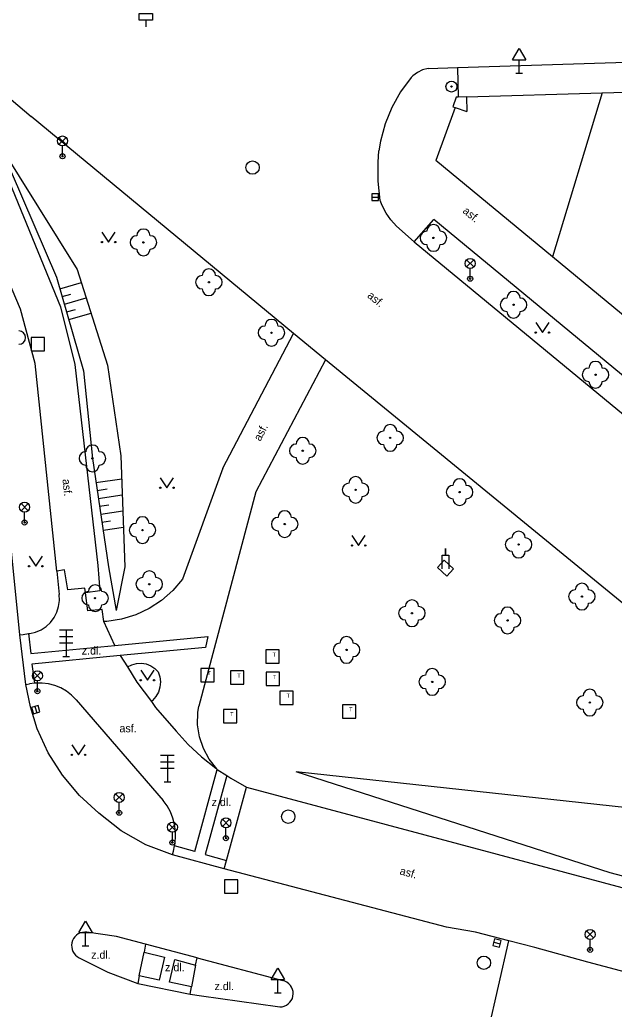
# Model space of a CAD drawing. Extents: x -642282 to -641982, y -1041678 to -1041427.
# Drawn here: x -642170.1 to -642125.6, y -1041580.5 to -1041506.3 of the extents above; entities that cross this region are included whole.
import ezdxf

# ---------------------------------------------------------------- set-up
doc = ezdxf.new("R2010")
doc.units = 0
for name, color, linetype in [('Ploty', 7, 'Continuous'), ('Pol_bod_pole', 7, 'Continuous'), ('Popis povrchů', 7, 'Continuous'), ('Rozhraní ploch 1', 7, 'Continuous'), ('Rozhraní ploch 2', 7, 'Continuous'), ('Ter_hr__hladina', 7, 'Continuous'), ('Vstup na pozemky', 7, 'Continuous'), ('Výšk_šrafy', 7, 'Continuous'), ('Zeleň - stromy', 7, 'Continuous'), ('Znaky doprava', 7, 'Continuous'), ('Znaky kanalizace', 7, 'Continuous'), ('Znaky voda', 7, 'Continuous'), ('Značky doprava', 7, 'Continuous'), ('Značky KM', 7, 'Continuous'), ('Šachta teplo', 7, 'Continuous'), ('Šachty ner_', 7, 'Continuous')]:
    doc.layers.add(name, color=color, linetype=linetype)

msp = doc.modelspace()

# ---------------------------------------------------------------- linework, layer by layer
at = {"layer": 'Ploty'}
for p, q in [((-642136.68, -1041512.12), (-642126.507, -1041511.827)), ((-642126.507, -1041511.827), (-642116.642, -1041511.542)), ((-642130.246, -1041524.117), (-642138.97, -1041516.89)), ((-642118.52, -1041533.83), (-642130.246, -1041524.117))]:
    msp.add_line(p, q, dxfattribs=at)
at = {"layer": 'Pol_bod_pole'}
for radius in [0.412, 0.05]:
    msp.add_circle((-642137.8, -1041511.35), radius, dxfattribs=at)
at = {"layer": 'Rozhraní ploch 1'}
for p, q in [((-642174.9, -1041508.88), (-642169.27, -1041513.6)), ((-642137.35, -1041509.91), (-642090.353, -1041508.419)), ((-642139.54, -1041510), (-642137.35, -1041509.91)), ((-642149.632, -1041529.862), (-642169.27, -1041513.6)), ((-642171.56, -1041516.94), (-642167.09, -1041527.87)), ((-642170.07, -1041528.03), (-642174.33, -1041518.1)), ((-642140.59, -1041523), (-642139.12, -1041521.31)), ((-642112.61, -1041543.25), (-642139.12, -1041521.31)), ((-642141.91, -1041521.82), (-642140.59, -1041523)), ((-642140.59, -1041523), (-642113.98, -1041544.965)), ((-642168.98, -1041532.12), (-642170.07, -1041528.03)), ((-642167.09, -1041527.87), (-642166.01, -1041532.18)), ((-642154.92, -1041539.96), (-642149.632, -1041529.862)), ((-642147.24, -1041531.84), (-642149.632, -1041529.862)), ((-642147.24, -1041531.84), (-642152.44, -1041541.74)), ((-642117.21, -1041556.47), (-642147.24, -1041531.84)), ((-642167.35, -1041547.67), (-642168.98, -1041532.12)), ((-642166.01, -1041532.18), (-642164.29, -1041547.24)), ((-642154.92, -1041539.96), (-642157.95, -1041548.28)), ((-642152.44, -1041541.74), (-642156.72, -1041557.79)), ((-642167.35, -1041547.67), (-642167.19, -1041549.43)), ((-642169.69, -1041556.17), (-642169.41, -1041556.13)), ((-642165.92, -1041557.31), (-642159.39, -1041564.87)), ((-642153.14, -1041563.87), (-642090.33, -1041580.69)), ((-642158.7, -1041568.93), (-642158.63, -1041568.66)), ((-642131.57, -1041575.9), (-642133.51, -1041575.39)), ((-642127.58, -1041576.99), (-642131.57, -1041575.9)), ((-642156.84, -1041576.65), (-642150.44, -1041578.37)), ((-642102.45, -1041583.73), (-642127.58, -1041576.99)), ((-642156.52, -1041579.52), (-642150.83, -1041580.32))]:
    msp.add_line(p, q, dxfattribs=at)
for points in [[(-642139.54, -1041510), (-642139.958, -1041510.106), (-642140.349, -1041510.288), (-642140.7, -1041510.538), (-642140.83, -1041510.66)], [(-642140.83, -1041510.66), (-642141.61, -1041511.746), (-642142.256, -1041512.917), (-642142.757, -1041514.156), (-642143.106, -1041515.447), (-642143.23, -1041516.16)], [(-642143.13, -1041519.89), (-642143.295, -1041518.454), (-642143.301, -1041517.009), (-642143.23, -1041516.16)], [(-642141.91, -1041521.82), (-642142.332, -1041521.349), (-642142.691, -1041520.829), (-642142.982, -1041520.268), (-642143.13, -1041519.89)], [(-642170.12, -1041552.46), (-642171.2, -1041541.67)], [(-642164.29, -1041547.24), (-642164.13, -1041549.14), (-642165.215, -1041549.289)], [(-642157.95, -1041548.28), (-642158.67, -1041549.13), (-642159.505, -1041549.868), (-642160.436, -1041550.479), (-642161.445, -1041550.95), (-642162.512, -1041551.272), (-642163.613, -1041551.438), (-642163.825, -1041551.45)], [(-642169.38, -1041552.34), (-642168.943, -1041552.239), (-642168.529, -1041552.064), (-642168.153, -1041551.819), (-642167.825, -1041551.513), (-642167.555, -1041551.154), (-642167.351, -1041550.754), (-642167.22, -1041550.324), (-642167.166, -1041549.878), (-642167.19, -1041549.43)], [(-642163.825, -1041551.45), (-642163.97, -1041550.56), (-642165.04, -1041550.64), (-642165.215, -1041549.289)], [(-642170.12, -1041552.46), (-642169.87, -1041552.42), (-642169.473, -1041552.355), (-642169.38, -1041552.34)], [(-642169.34, -1041557.852), (-642169.69, -1041556.17), (-642170.12, -1041552.46)], [(-642162.06, -1041554.86), (-642161.737, -1041554.687), (-642161.383, -1041554.589), (-642161.017, -1041554.569), (-642160.656, -1041554.629), (-642160.316, -1041554.766), (-642160.013, -1041554.973), (-642159.77, -1041555.23)], [(-642159.77, -1041555.23), (-642159.647, -1041555.596), (-642159.602, -1041555.98), (-642159.636, -1041556.365), (-642159.749, -1041556.735), (-642159.936, -1041557.073), (-642160.188, -1041557.367), (-642160.27, -1041557.44)], [(-642165.92, -1041557.31), (-642166.26, -1041556.967), (-642166.641, -1041556.672), (-642167.059, -1041556.43), (-642167.505, -1041556.246), (-642167.971, -1041556.122), (-642168.45, -1041556.061), (-642168.932, -1041556.064), (-642169.04, -1041556.08), (-642169.41, -1041556.13)], [(-642168, -1041561.292), (-642168.82, -1041559.49), (-642169.34, -1041557.852)], [(-642155.338, -1041562.535), (-642155.367, -1041562.482), (-642155.941, -1041561.766), (-642156.381, -1041560.961), (-642156.675, -1041560.092), (-642156.815, -1041559.185), (-642156.795, -1041558.267), (-642156.72, -1041557.79)], [(-642162.544, -1041567.143), (-642164.2, -1041565.81), (-642165.669, -1041564.482), (-642166.943, -1041562.967), (-642168, -1041561.292)], [(-642155.338, -1041562.535), (-642154.636, -1041563.001), (-642154.328, -1041563.206), (-642153.14, -1041563.87)], [(-642158.63, -1041568.66), (-642158.538, -1041568.269), (-642158.515, -1041568.171), (-642158.46, -1041567.671), (-642158.467, -1041567.168), (-642158.536, -1041566.67), (-642158.665, -1041566.184), (-642158.852, -1041565.717), (-642159.095, -1041565.277), (-642159.39, -1041564.87)], [(-642154.82, -1041570), (-642158.7, -1041568.93), (-642160.694, -1041568.192), (-642162.544, -1041567.143)], [(-642138.17, -1041574.37), (-642154.82, -1041570)], [(-642156.84, -1041576.65), (-642160.71, -1041575.63), (-642162.882, -1041575.073), (-642165.1, -1041574.74), (-642165.268, -1041574.732), (-642165.435, -1041574.751), (-642165.597, -1041574.798), (-642165.748, -1041574.871), (-642165.886, -1041574.968), (-642166.005, -1041575.087), (-642166.104, -1041575.223), (-642166.178, -1041575.374)], [(-642133.51, -1041575.39), (-642135.99, -1041574.73), (-642138.17, -1041574.37)], [(-642166.178, -1041575.374), (-642166.23, -1041575.55), (-642166.248, -1041575.702), (-642166.242, -1041575.87), (-642166.208, -1041576.035), (-642166.147, -1041576.192), (-642166.061, -1041576.336), (-642165.953, -1041576.465), (-642165.824, -1041576.574), (-642165.68, -1041576.66), (-642163.54, -1041577.74), (-642161.3, -1041578.58)], [(-642161.3, -1041578.58), (-642157.37, -1041579.38), (-642156.52, -1041579.52)], [(-642150.83, -1041580.32), (-642150.659, -1041580.337), (-642150.487, -1041580.325), (-642150.32, -1041580.283), (-642150.163, -1041580.213), (-642150.02, -1041580.116), (-642149.896, -1041579.997), (-642149.794, -1041579.858), (-642149.718, -1041579.703), (-642149.67, -1041579.538), (-642149.651, -1041579.367), (-642149.662, -1041579.195), (-642149.702, -1041579.028), (-642149.771, -1041578.87), (-642149.865, -1041578.726), (-642149.983, -1041578.601), (-642150.122, -1041578.498), (-642150.275, -1041578.42), (-642150.44, -1041578.37)]]:
    msp.add_lwpolyline(points, dxfattribs=at)
at = {"layer": 'Rozhraní ploch 2'}
for p, q in [((-642137.35, -1041509.91), (-642137.287, -1041512.136)), ((-642126.507, -1041511.827), (-642130.246, -1041524.117)), ((-642137.44, -1041512.14), (-642137.69, -1041512.86)), ((-642136.68, -1041512.12), (-642136.651, -1041513.221)), ((-642138.84, -1041547.39), (-642138.36, -1041546.85)), ((-642138.14, -1041548.05), (-642138.84, -1041547.39)), ((-642137.66, -1041547.51), (-642138.36, -1041546.85)), ((-642137.66, -1041547.51), (-642138.14, -1041548.05)), ((-642163.014, -1041553.237), (-642163.825, -1041551.45)), ((-642169.473, -1041552.355), (-642169.31, -1041553.84)), ((-642163.014, -1041553.237), (-642156.04, -1041552.57)), ((-642156.04, -1041552.57), (-642156.23, -1041553.39)), ((-642169.31, -1041553.84), (-642163.014, -1041553.237)), ((-642156.23, -1041553.39), (-642162.602, -1041554.003)), ((-642162.602, -1041554.003), (-642169.23, -1041554.64)), ((-642169.23, -1041554.64), (-642169.04, -1041556.08)), ((-642157.01, -1041568.69), (-642155.338, -1041562.535)), ((-642154.636, -1041563.001), (-642156.24, -1041568.92)), ((-642154.645, -1041569.36), (-642153.14, -1041563.87)), ((-642157.01, -1041568.69), (-642158.538, -1041568.269)), ((-642156.24, -1041568.92), (-642154.645, -1041569.36)), ((-642154.82, -1041570), (-642154.645, -1041569.36)), ((-642160.71, -1041575.63), (-642160.82, -1041576.23)), ((-642161.18, -1041578.02), (-642160.82, -1041576.23)), ((-642156.96, -1041577.2), (-642156.84, -1041576.65)), ((-642156.96, -1041577.2), (-642157.28, -1041578.83)), ((-642161.18, -1041578.02), (-642161.3, -1041578.58)), ((-642157.37, -1041579.38), (-642157.28, -1041578.83))]:
    msp.add_line(p, q, dxfattribs=at)
for points in [[(-642136.68, -1041512.12), (-642137.287, -1041512.136), (-642137.44, -1041512.14)], [(-642137.69, -1041512.86), (-642137.518, -1041512.92), (-642136.651, -1041513.221)], [(-642165.215, -1041549.289), (-642165.26, -1041548.94), (-642166.53, -1041549.08), (-642166.78, -1041547.58), (-642167.35, -1041547.67)], [(-642162.602, -1041554.003), (-642162.06, -1041554.86), (-642161.373, -1041556.004), (-642160.27, -1041557.44), (-642159.979, -1041557.894), (-642158.43, -1041559.66)], [(-642158.43, -1041559.66), (-642157.516, -1041560.669), (-642156.523, -1041561.6), (-642155.458, -1041562.448), (-642155.338, -1041562.535)], [(-642135.06, -1041582.18), (-642133.51, -1041575.39)], [(-642160.82, -1041576.23), (-642159.29, -1041576.6), (-642159.69, -1041578.33), (-642161.18, -1041578.02)], [(-642157.28, -1041578.83), (-642158.91, -1041578.49), (-642158.52, -1041576.79), (-642156.96, -1041577.2)]]:
    msp.add_lwpolyline(points, dxfattribs=at)
at = {"layer": 'Ter_hr__hladina'}
for p, q in [((-642171.64, -1041515.78), (-642167.38, -1041525.63)), ((-642171.64, -1041515.78), (-642165.83, -1041525.06)), ((-642165.83, -1041525.06), (-642163.55, -1041532.24)), ((-642167.38, -1041525.63), (-642165.36, -1041532.65)), ((-642165.36, -1041532.65), (-642164.69, -1041539.22)), ((-642163.55, -1041532.24), (-642162.56, -1041539.03)), ((-642164.69, -1041539.22), (-642163.49, -1041547.36)), ((-642162.56, -1041539.03), (-642162.27, -1041547.34)), ((-642163.49, -1041547.36), (-642162.91, -1041550.62)), ((-642162.27, -1041547.34), (-642162.91, -1041550.62)), ((-642125.91, -1041570.28), (-642149.42, -1041562.73)), ((-642124.62, -1041565.42), (-642149.42, -1041562.73)), ((-642100.72, -1041577.07), (-642125.91, -1041570.28))]:
    msp.add_line(p, q, dxfattribs=at)
at = {"layer": 'Vstup na pozemky'}
msp.add_line((-642137.518, -1041512.92), (-642138.97, -1041516.89), dxfattribs=at)
at = {"layer": 'Výšk_šrafy'}
for p, q in [((-642167.126, -1041526.512), (-642165.516, -1041526.049)), ((-642166.96, -1041527.088), (-642166.31, -1041526.901)), ((-642166.794, -1041527.665), (-642165.153, -1041527.193)), ((-642166.628, -1041528.242), (-642165.965, -1041528.051)), ((-642166.463, -1041528.818), (-642164.79, -1041528.336)), ((-642164.423, -1041541.033), (-642162.5, -1041540.749)), ((-642164.335, -1041541.626), (-642163.593, -1041541.517)), ((-642164.248, -1041542.22), (-642162.458, -1041541.956)), ((-642164.16, -1041542.814), (-642163.471, -1041542.712)), ((-642164.073, -1041543.407), (-642162.416, -1041543.163)), ((-642163.985, -1041544.001), (-642163.349, -1041543.907)), ((-642163.898, -1041544.594), (-642162.374, -1041544.369))]:
    msp.add_line(p, q, dxfattribs=at)
at = {"layer": 'Zeleň - stromy'}
for centre in [(-642160.87, -1041523.03), (-642139.15, -1041522.7), (-642155.97, -1041526.02), (-642133.15, -1041527.71), (-642151.28, -1041529.8), (-642127.01, -1041532.95), (-642142.39, -1041537.69), (-642148.94, -1041538.65), (-642164.69, -1041539.22), (-642144.98, -1041541.58), (-642137.19, -1041541.75), (-642150.29, -1041544.15), (-642160.94, -1041544.6), (-642132.77, -1041545.68), (-642160.43, -1041548.66), (-642164.49, -1041549.7), (-642128.03, -1041549.58), (-642140.76, -1041550.83), (-642133.6, -1041551.37), (-642145.66, -1041553.58), (-642139.24, -1041555.98), (-642127.44, -1041557.53)]:
    msp.add_circle(centre, 0.05, dxfattribs=at)
for centre, start, end in [((-642160.87, -1041522.53), 0, 180), ((-642139.65, -1041522.7), 90, 270), ((-642139.15, -1041522.2), 0, 180), ((-642138.65, -1041522.7), 270, 90), ((-642161.37, -1041523.03), 90, 270), ((-642160.37, -1041523.03), 270, 90), ((-642160.87, -1041523.53), 180, 0), ((-642139.15, -1041523.2), 180, 0), ((-642155.97, -1041525.52), 0, 180), ((-642156.47, -1041526.02), 90, 270), ((-642155.47, -1041526.02), 270, 90), ((-642155.97, -1041526.52), 180, 0), ((-642133.15, -1041527.21), 0, 180), ((-642133.65, -1041527.71), 90, 270), ((-642132.65, -1041527.71), 270, 90), ((-642133.15, -1041528.21), 180, 0), ((-642151.28, -1041529.3), 0, 180), ((-642170.2, -1041530.17), 270, 90), ((-642151.78, -1041529.8), 90, 270), ((-642150.78, -1041529.8), 270, 90), ((-642151.28, -1041530.3), 180, 0), ((-642127.51, -1041532.95), 90, 270), ((-642127.01, -1041532.45), 0, 180), ((-642126.51, -1041532.95), 270, 90), ((-642127.01, -1041533.45), 180, 0), ((-642142.39, -1041537.19), 0, 180), ((-642148.94, -1041538.15), 0, 180), ((-642142.89, -1041537.69), 90, 270), ((-642141.89, -1041537.69), 270, 90), ((-642164.69, -1041538.72), 0, 180), ((-642149.44, -1041538.65), 90, 270), ((-642148.44, -1041538.65), 270, 90), ((-642142.39, -1041538.19), 180, 0), ((-642165.19, -1041539.22), 90, 270), ((-642164.19, -1041539.22), 270, 90), ((-642148.94, -1041539.15), 180, 0), ((-642164.69, -1041539.72), 180, 0), ((-642144.98, -1041541.08), 0, 180), ((-642137.19, -1041541.25), 0, 180), ((-642145.48, -1041541.58), 90, 270), ((-642144.48, -1041541.58), 270, 90), ((-642137.69, -1041541.75), 90, 270), ((-642136.69, -1041541.75), 270, 90), ((-642144.98, -1041542.08), 180, 0), ((-642137.19, -1041542.25), 180, 0), ((-642160.94, -1041544.1), 0, 180), ((-642150.79, -1041544.15), 90, 270), ((-642150.29, -1041543.65), 0, 180), ((-642149.79, -1041544.15), 270, 90), ((-642161.44, -1041544.6), 90, 270), ((-642160.44, -1041544.6), 270, 90), ((-642160.94, -1041545.1), 180, 0), ((-642150.29, -1041544.65), 180, 0), ((-642133.27, -1041545.68), 90, 270), ((-642132.77, -1041545.18), 0, 180), ((-642132.27, -1041545.68), 270, 90), ((-642132.77, -1041546.18), 180, 0), ((-642160.93, -1041548.66), 90, 270), ((-642160.43, -1041548.16), 0, 180), ((-642159.93, -1041548.66), 270, 90), ((-642164.49, -1041549.2), 0, 180), ((-642128.03, -1041549.08), 0, 180), ((-642164.99, -1041549.7), 90, 270), ((-642163.99, -1041549.7), 270, 90), ((-642160.43, -1041549.16), 180, 0), ((-642128.53, -1041549.58), 90, 270), ((-642127.53, -1041549.58), 270, 90), ((-642164.49, -1041550.2), 180, 0), ((-642141.26, -1041550.83), 90, 270), ((-642140.76, -1041550.33), 0, 180), ((-642140.26, -1041550.83), 270, 90), ((-642133.6, -1041550.87), 0, 180), ((-642128.03, -1041550.08), 180, 0), ((-642134.1, -1041551.37), 90, 270), ((-642133.1, -1041551.37), 270, 90), ((-642140.76, -1041551.33), 180, 0), ((-642133.6, -1041551.87), 180, 0), ((-642145.66, -1041553.08), 0, 180), ((-642146.16, -1041553.58), 90, 270), ((-642145.16, -1041553.58), 270, 90), ((-642145.66, -1041554.08), 180, 0), ((-642139.74, -1041555.98), 90, 270), ((-642139.24, -1041555.48), 0, 180), ((-642138.74, -1041555.98), 270, 90), ((-642139.24, -1041556.48), 180, 0), ((-642127.94, -1041557.53), 90, 270), ((-642127.44, -1041557.03), 0, 180), ((-642126.94, -1041557.53), 270, 90), ((-642127.44, -1041558.03), 180, 0)]:
    msp.add_arc(centre, 0.5, start, end, dxfattribs=at)
at = {"layer": 'Znaky doprava'}
for p, q in [((-642167.195, -1041515.165), (-642166.665, -1041515.695)), ((-642167.195, -1041515.695), (-642166.665, -1041515.165)), ((-642166.93, -1041516.58), (-642166.93, -1041515.805)), ((-642136.665, -1041524.345), (-642136.135, -1041524.875)), ((-642136.665, -1041524.875), (-642136.135, -1041524.345)), ((-642136.4, -1041525.76), (-642136.4, -1041524.985)), ((-642170.035, -1041542.615), (-642169.505, -1041543.145)), ((-642170.035, -1041543.145), (-642169.505, -1041542.615)), ((-642169.77, -1041544.03), (-642169.77, -1041543.255)), ((-642167.15, -1041552.08), (-642166.15, -1041552.08)), ((-642167.15, -1041552.58), (-642166.15, -1041552.58)), ((-642166.65, -1041552.08), (-642166.65, -1041554.08)), ((-642166.15, -1041553.08), (-642167.15, -1041553.08)), ((-642166.9, -1041554.08), (-642166.4, -1041554.08)), ((-642169.075, -1041555.255), (-642168.545, -1041555.785)), ((-642169.075, -1041555.785), (-642168.545, -1041555.255)), ((-642168.81, -1041556.67), (-642168.81, -1041555.895)), ((-642159.58, -1041561.47), (-642158.58, -1041561.47)), ((-642159.08, -1041561.47), (-642159.08, -1041563.47)), ((-642159.58, -1041561.97), (-642158.58, -1041561.97)), ((-642158.58, -1041562.47), (-642159.58, -1041562.47)), ((-642159.33, -1041563.47), (-642158.83, -1041563.47)), ((-642162.955, -1041564.375), (-642162.425, -1041564.905)), ((-642162.955, -1041564.905), (-642162.425, -1041564.375)), ((-642162.69, -1041565.79), (-642162.69, -1041565.015)), ((-642158.965, -1041566.605), (-642158.435, -1041567.135)), ((-642158.965, -1041567.135), (-642158.435, -1041566.605)), ((-642154.955, -1041566.275), (-642154.425, -1041566.805)), ((-642154.955, -1041566.805), (-642154.425, -1041566.275)), ((-642158.7, -1041568.02), (-642158.7, -1041567.245)), ((-642154.69, -1041567.69), (-642154.69, -1041566.915)), ((-642127.685, -1041574.645), (-642127.155, -1041575.175)), ((-642127.685, -1041575.175), (-642127.155, -1041574.645)), ((-642127.42, -1041576.06), (-642127.42, -1041575.285))]:
    msp.add_line(p, q, dxfattribs=at)
for centre, radius in [((-642166.93, -1041515.43), 0.375), ((-642166.93, -1041516.58), 0.19), ((-642166.93, -1041516.58), 0.05), ((-642136.4, -1041524.61), 0.375), ((-642136.4, -1041525.76), 0.19), ((-642136.4, -1041525.76), 0.05), ((-642169.77, -1041542.88), 0.375), ((-642169.77, -1041544.03), 0.19), ((-642169.77, -1041544.03), 0.05), ((-642168.81, -1041555.52), 0.375), ((-642168.81, -1041556.67), 0.19), ((-642168.81, -1041556.67), 0.05), ((-642162.69, -1041564.64), 0.375), ((-642162.69, -1041565.79), 0.19), ((-642162.69, -1041565.79), 0.05), ((-642158.7, -1041566.87), 0.375), ((-642154.69, -1041566.54), 0.375), ((-642154.69, -1041567.69), 0.19), ((-642158.7, -1041568.02), 0.19), ((-642158.7, -1041568.02), 0.05), ((-642154.69, -1041567.69), 0.05), ((-642127.42, -1041574.91), 0.375), ((-642127.42, -1041576.06), 0.19), ((-642127.42, -1041576.06), 0.05)]:
    msp.add_circle(centre, radius, dxfattribs=at)
at = {"layer": 'Znaky kanalizace'}
for p, q in [((-642143.76, -1041519.63), (-642143.26, -1041519.63)), ((-642169.002, -1041557.821), (-642168.858, -1041558.299)), ((-642134.632, -1041575.486), (-642134.148, -1041575.614))]:
    msp.add_line(p, q, dxfattribs=at)
for points in [[(-642143.76, -1041519.88), (-642143.26, -1041519.88), (-642143.26, -1041519.38), (-642143.76, -1041519.38)], [(-642169.241, -1041557.892), (-642169.098, -1041558.371), (-642168.619, -1041558.228), (-642168.762, -1041557.749)], [(-642134.696, -1041575.727), (-642134.213, -1041575.856), (-642134.084, -1041575.373), (-642134.567, -1041575.244)]]:
    msp.add_lwpolyline(points, close=True, dxfattribs=at)
for centre in [(-642152.7, -1041517.42), (-642150.02, -1041566.08), (-642135.37, -1041577.03)]:
    msp.add_circle(centre, 0.5, dxfattribs=at)
at = {"layer": 'Znaky voda'}
msp.add_line((-642160.69, -1041506.37), (-642160.69, -1041506.87), dxfattribs=at)
msp.add_lwpolyline([(-642160.19, -1041505.87), (-642160.19, -1041506.37), (-642161.19, -1041506.37), (-642161.19, -1041505.87), (-642160.19, -1041505.87)], dxfattribs=at)
at = {"layer": 'Značky doprava'}
for p, q in [((-642133.22, -1041509.34), (-642132.72, -1041508.49)), ((-642132.72, -1041508.49), (-642132.22, -1041509.34)), ((-642133.22, -1041509.34), (-642132.22, -1041509.34)), ((-642132.72, -1041510.34), (-642132.72, -1041509.34)), ((-642132.97, -1041510.34), (-642132.47, -1041510.34)), ((-642165.71, -1041574.76), (-642165.21, -1041573.91)), ((-642165.21, -1041573.91), (-642164.71, -1041574.76)), ((-642165.71, -1041574.76), (-642164.71, -1041574.76)), ((-642165.21, -1041575.76), (-642165.21, -1041574.76)), ((-642165.459, -1041575.76), (-642164.961, -1041575.76)), ((-642151.3, -1041578.28), (-642150.8, -1041577.43)), ((-642150.8, -1041577.43), (-642150.3, -1041578.28)), ((-642151.3, -1041578.28), (-642150.3, -1041578.28)), ((-642150.8, -1041579.28), (-642150.8, -1041578.28)), ((-642151.049, -1041579.28), (-642150.551, -1041579.28))]:
    msp.add_line(p, q, dxfattribs=at)
at = {"layer": 'Značky KM'}
for p, q in [((-642163.98, -1041522.259), (-642163.48, -1041523.009)), ((-642163.48, -1041523.009), (-642162.98, -1041522.259)), ((-642131.494, -1041529.045), (-642130.994, -1041529.795)), ((-642130.994, -1041529.795), (-642130.494, -1041529.045)), ((-642159.607, -1041540.67), (-642159.107, -1041541.42)), ((-642159.107, -1041541.42), (-642158.607, -1041540.67)), ((-642145.26, -1041545.001), (-642144.76, -1041545.751)), ((-642144.76, -1041545.751), (-642144.26, -1041545.001)), ((-642138.26, -1041546.49), (-642138.26, -1041545.99)), ((-642138.26, -1041545.99), (-642138.26, -1041546.49)), ((-642169.436, -1041546.56), (-642168.936, -1041547.31)), ((-642168.936, -1041547.31), (-642168.436, -1041546.56)), ((-642138.51, -1041547.49), (-642138.51, -1041546.49)), ((-642138.51, -1041546.49), (-642138.26, -1041546.49)), ((-642138.26, -1041546.49), (-642138.01, -1041546.49)), ((-642138.01, -1041546.49), (-642138.01, -1041547.49)), ((-642161.077, -1041555.104), (-642160.577, -1041555.854)), ((-642160.577, -1041555.854), (-642160.077, -1041555.104)), ((-642166.232, -1041560.706), (-642165.732, -1041561.456)), ((-642165.732, -1041561.456), (-642165.232, -1041560.706))]:
    msp.add_line(p, q, dxfattribs=at)
for centre in [(-642163.98, -1041523.009), (-642162.98, -1041523.009), (-642131.494, -1041529.795), (-642130.494, -1041529.795), (-642159.607, -1041541.42), (-642158.607, -1041541.42), (-642145.26, -1041545.751), (-642144.26, -1041545.751), (-642169.436, -1041547.31), (-642168.436, -1041547.31), (-642161.077, -1041555.854), (-642160.077, -1041555.854), (-642166.232, -1041561.456), (-642165.232, -1041561.456)]:
    msp.add_circle(centre, 0.05, dxfattribs=at)
at = {"layer": 'Šachta teplo'}
for points in [[(-642151.7, -1041554.58), (-642150.7, -1041554.58), (-642150.7, -1041553.58), (-642151.7, -1041553.58)], [(-642156.58, -1041555.97), (-642155.58, -1041555.97), (-642155.58, -1041554.97), (-642156.58, -1041554.97)], [(-642154.34, -1041556.15), (-642153.34, -1041556.15), (-642153.34, -1041555.15), (-642154.34, -1041555.15)], [(-642151.68, -1041556.26), (-642150.68, -1041556.26), (-642150.68, -1041555.26), (-642151.68, -1041555.26)], [(-642150.65, -1041557.66), (-642149.65, -1041557.66), (-642149.65, -1041556.66), (-642150.65, -1041556.66)], [(-642145.96, -1041558.69), (-642144.96, -1041558.69), (-642144.96, -1041557.69), (-642145.96, -1041557.69)], [(-642154.88, -1041559.04), (-642153.88, -1041559.04), (-642153.88, -1041558.04), (-642154.88, -1041558.04)]]:
    msp.add_lwpolyline(points, close=True, dxfattribs=at)
at = {"layer": 'Šachty ner_'}
for points in [[(-642169.27, -1041531.15), (-642168.27, -1041531.15), (-642168.27, -1041530.15), (-642169.27, -1041530.15)], [(-642154.8, -1041571.82), (-642153.8, -1041571.82), (-642153.8, -1041570.82), (-642154.8, -1041570.82)]]:
    msp.add_lwpolyline(points, close=True, dxfattribs=at)

# ---------------------------------------------------------------- texts
at = {"layer": 'Popis povrchů'}
for rotation, p in [(320.64209, (-642137.011, -1041520.765)), (320.64209, (-642144.153, -1041527.109)), (62.28919, (-642152.116, -1041537.979)), (275.97759, (-642166.94, -1041540.795)), (345.17407, (-642141.721, -1041570.399))]:
    msp.add_text('asf.', height=0.6, rotation=rotation, dxfattribs=at).set_placement(p)
for s, p in [('z.dl.', (-642165.492, -1041553.93)), ('asf.', (-642162.667, -1041559.751)), ('z.dl.', (-642155.766, -1041565.285)), ('z.dl.', (-642164.786, -1041576.731)), ('z.dl.', (-642159.251, -1041577.668)), ('z.dl.', (-642155.55, -1041579.084))]:
    msp.add_text(s, height=0.6, dxfattribs=at).set_placement(p)
at = {"layer": 'Šachta teplo'}
for p in [(-642151.2, -1041554.08), (-642156.08, -1041555.47), (-642153.84, -1041555.65), (-642151.18, -1041555.76), (-642150.15, -1041557.16), (-642154.38, -1041558.54), (-642145.46, -1041558.19)]:
    msp.add_text('T', height=0.3, dxfattribs=at).set_placement(p)

doc.saveas('drawing.dxf')
